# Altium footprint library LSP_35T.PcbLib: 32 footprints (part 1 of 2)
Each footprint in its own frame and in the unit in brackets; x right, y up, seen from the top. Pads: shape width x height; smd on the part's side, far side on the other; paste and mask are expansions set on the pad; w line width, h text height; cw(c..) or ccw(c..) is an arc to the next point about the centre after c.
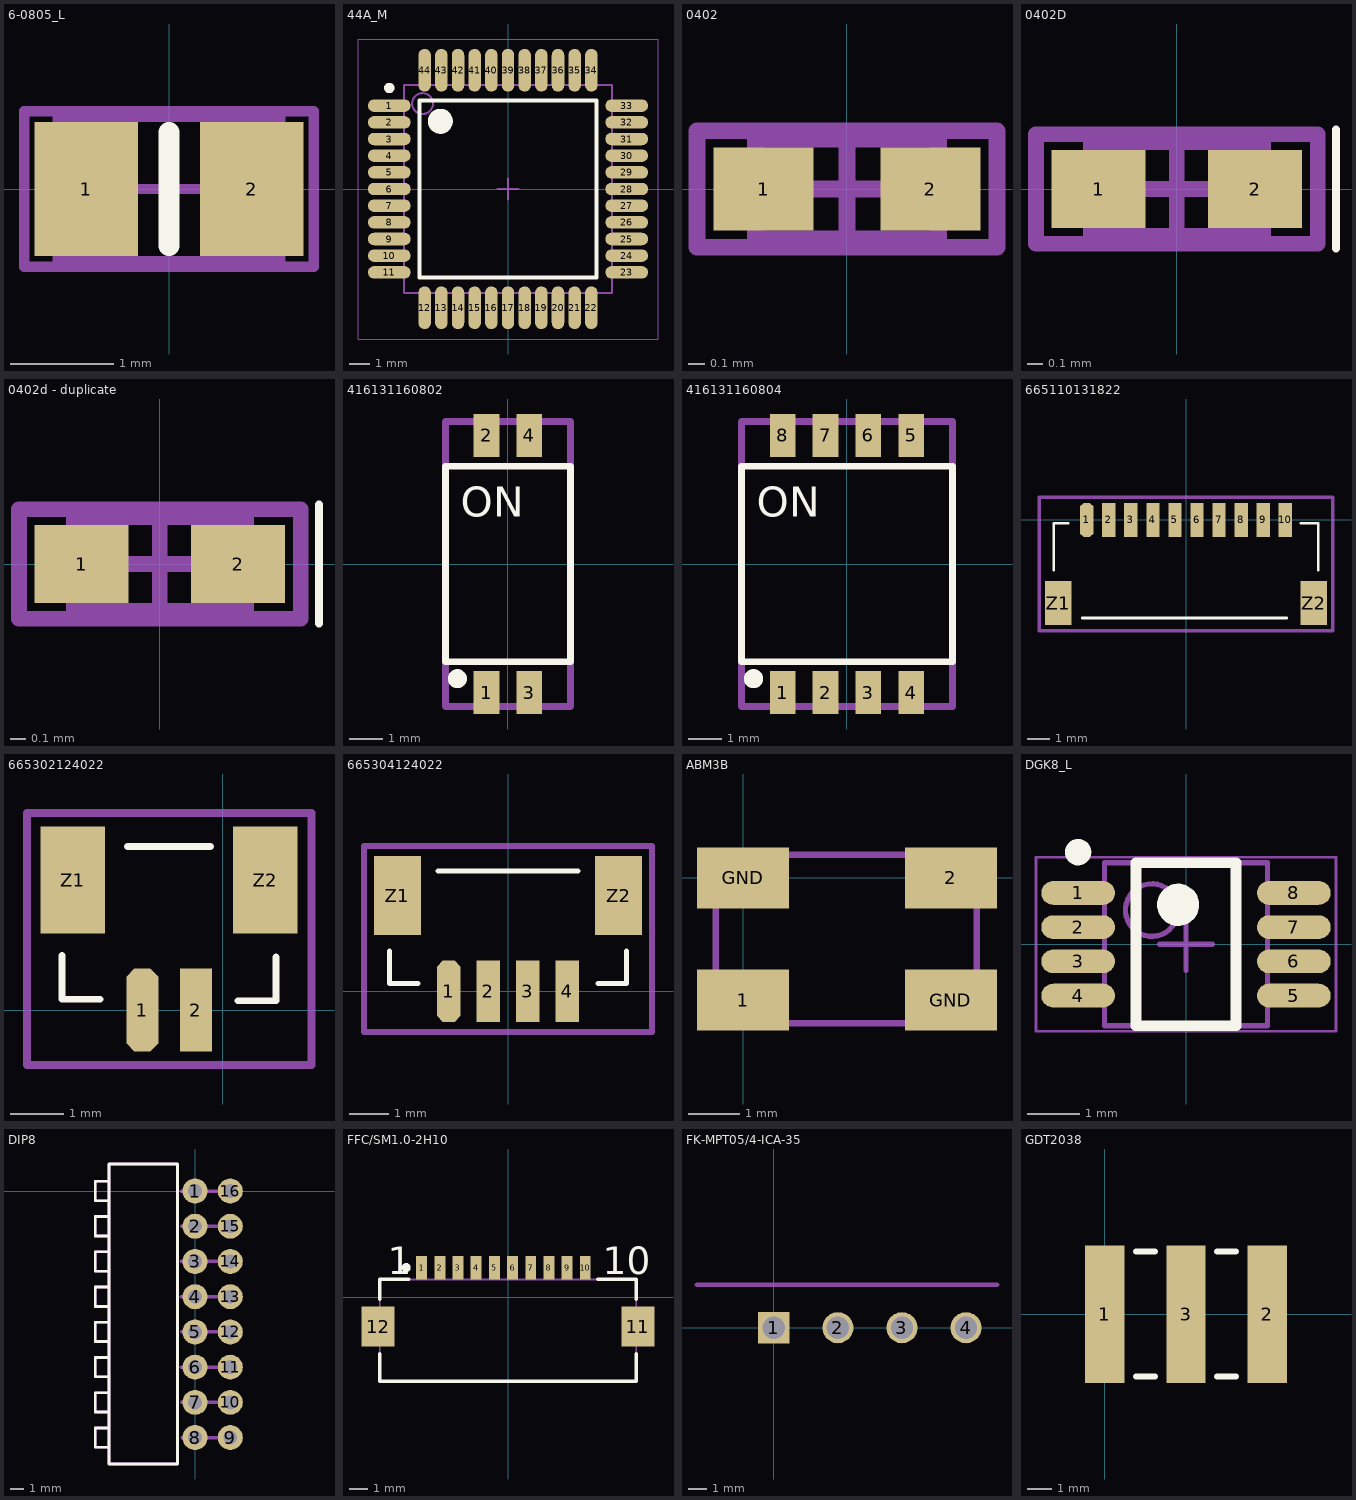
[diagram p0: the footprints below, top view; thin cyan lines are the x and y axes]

## 6-0805_L [mm] "Chip Resistor, Body 2.0x1.2mm, IPC High Density"
height 0.7
pads (2):
  rect 1x1.3 smd: 1(-0.8,0) 2(0.8,0)
Top Overlay:
  lines w0.2: 0,-0.55 0,0.55
Mechanical 13:
  lines w0.1: -1.075,-0.7 -1.075,0.7 1.075,0.7 1.075,-0.7 -1.075,-0.7
Mechanical 15:
  lines w0.1: -0.5,0 0.5,0 ; 0,-0.5 0,0.5 ; -1.4,-0.75 -1.4,0.75 1.4,0.75 1.4,-0.75 -1.4,-0.75
3D body: height 0.7, standoff 0, extent -1.075,-0.7 1.075,0.7

## 44A_M [mm] "Thin QFP, 44-Leads, Body 10x10mm, Pitch 0.8mm, IPC Low Density"
height 1.2
pads (44):
  oval 2.05x0.6 smd: 1(-5.7,4) 2(-5.7,3.2) 3(-5.7,2.4) 4(-5.7,1.6) 5(-5.7,0.8) 6(-5.7,0) 7(-5.7,-0.8) 8(-5.7,-1.6) 9(-5.7,-2.4) 10(-5.7,-3.2) 11(-5.7,-4) 23(5.7,-4) 24(5.7,-3.2) 25(5.7,-2.4) 26(5.7,-1.6) 27(5.7,-0.8) 28(5.7,0) 29(5.7,0.8) 30(5.7,1.6) 31(5.7,2.4) 32(5.7,3.2) 33(5.7,4)
  oval 0.6x2.05 smd: 12(-4,-5.7) 13(-3.2,-5.7) 14(-2.4,-5.7) 15(-1.6,-5.7) 16(-0.8,-5.7) 17(0,-5.7) 18(0.8,-5.7) 19(1.6,-5.7) 20(2.4,-5.7) 21(3.2,-5.7) 22(4,-5.7) 34(4,5.7) 35(3.2,5.7) 36(2.4,5.7) 37(1.6,5.7) 38(0.8,5.7) 39(0,5.7) 40(-0.8,5.7) 41(-1.6,5.7) 42(-2.4,5.7) 43(-3.2,5.7) 44(-4,5.7)
Top Overlay:
  circle w0.6: c-3.25,3.25 r0.3
  circle w0.25: c-5.7,4.85 r0.125
  lines w0.2: -4.25,-4.25 4.25,-4.25 4.25,4.25 -4.25,4.25 -4.25,-4.25
Mechanical 13:
  circle w0.1: c-4.1,4.1 r0.5
  lines w0.1: -5,-5 5,-5 5,5 -5,5 -5,-5
Mechanical 15:
  lines w0.05: -7.2,-7.2 7.2,-7.2 7.2,7.2 -7.2,7.2 -7.2,-7.2
  lines w0.1: -0.5,0 0.5,0 ; 0,-0.5 0,0.5
3D body: height 1.2, standoff 0, extent -5,-5 5,5

## 0402 [mm] "Chip Capacitor, Body 1.0x0.5mm, IPC High Density"
height 1.3
pads (2):
  rect 0.6x0.5 smd: 1(-0.5,0) 2(0.5,0)
Mechanical 13:
  lines w0.1: -0.55,-0.3 -0.55,0.3 0.55,0.3 0.55,-0.3 -0.55,-0.3
Mechanical 15:
  lines w0.1: -0.3,0 0.3,0 ; 0,-0.3 0,0.3 ; -0.9,-0.35 -0.9,0.35 0.9,0.35 0.9,-0.35 -0.9,-0.35
3D body: height 1.3, standoff 0, extent -0.55,-0.3 0.55,0.3

## 0402D [mm] "Diode, Body 1.0x0.5mm, IPC High Density"
height 1.3
pads (2):
  rect 0.6x0.5 smd: 1(-0.5,0) 2(0.5,0)
Top Overlay:
  lines w0.051: 1.016,-0.381 1.016,0.381
Mechanical 13:
  lines w0.1: -0.55,-0.3 0.55,-0.3 0.55,0.3 -0.55,0.3 -0.55,-0.3
Mechanical 15:
  lines w0.1: -0.3,0 0.3,0 ; 0,-0.3 0,0.3 ; -0.9,-0.35 0.9,-0.35 0.9,0.35 -0.9,0.35 -0.9,-0.35

## 0402d - duplicate [mm]
pads (2):
  rect 0.6x0.5 smd: 1(-0.5,0) 2(0.5,0)
Top Overlay:
  lines w0.051: 1.016,-0.381 1.016,0.381
Mechanical 13:
  lines w0.1: -0.55,-0.3 0.55,-0.3 0.55,0.3 -0.55,0.3 -0.55,-0.3
Mechanical 15:
  lines w0.1: -0.3,0 0.3,0 ; 0,-0.3 0,0.3 ; -0.9,-0.35 0.9,-0.35 0.9,0.35 -0.9,0.35 -0.9,-0.35

## 416131160802 [mm] "1.27 mm small compact SMD flat actuator with top tape, 02p"
height 2.5
pads (4):
  rect 0.76x1.27 smd: 1(-0.635,-3.81) 2(-0.635,3.81) 3(0.635,-3.81) 4(0.635,3.81)
Top Overlay:
  circle w0.5: c-1.5,-3.4 r0.032
  lines w0.2: -1.855,-2.9 1.855,-2.9 1.855,2.9 -1.855,2.9 -1.855,-2.9
  text "ON" at -1.4,1.4 h0.89
Mechanical 13:
  lines w0.2: -1.855,-4.22 1.855,-4.22 1.855,4.22 -1.855,4.22 -1.855,-4.22
3D body: height 2.7, standoff 0, extent -1.855,-4.22 1.855,4.22

## 416131160804 [mm] "1.27 mm small compact SMD flat actuator with top tape, 04p"
height 2.5
pads (8):
  rect 0.76x1.27 smd: 1(-1.905,-3.81) 2(-0.635,-3.81) 3(0.635,-3.81) 4(1.905,-3.81) 5(1.905,3.81) 6(0.635,3.81) 7(-0.635,3.81) 8(-1.905,3.81)
Top Overlay:
  circle w0.5: c-2.77,-3.4 r0.032
  lines w0.2: -3.125,-2.9 -3.125,2.9 3.125,2.9 3.125,-2.9 -3.125,-2.9
  text "ON" at -2.67,1.4 h0.89
Mechanical 13:
  lines w0.2: -3.125,-4.22 -3.125,4.22 3.125,4.22 3.125,-4.22 -3.125,-4.22
3D body: height 2.7, standoff 0, extent -3.125,-4.22 3.125,4.22

## 665110131822 [mm] "ConWTB Wire-to-Board Connectors 1.00 mm SMT Male Horizontal Shrouded Header, 10 pins - Tape & Reel"
height 2.9
pads (12):
  oct 0.6x1.55 smd: 1(-4.5,0)
  rect 0.6x1.55 smd: 2(-3.5,0) 3(-2.5,0) 4(-1.5,0) 5(-0.5,0) 6(0.5,0) 7(1.5,0) 8(2.5,0) 9(3.5,0) 10(4.5,0)
  rect 1.2x2 smd: Z1(-5.8,-3.775) Z2(5.8,-3.775)
Top Overlay:
  lines w0.12: -6,-2.286 -6,-0.15 -5.334,-0.15 ; -4.699,-4.445 4.572,-4.445 ; 5.207,-0.15 6,-0.15 6,-2.286
Mechanical 15:
  lines w0.152: -6.65,-5.025 6.65,-5.025 6.65,1.025 -6.65,1.025 -6.65,-5.025
3D body: height 2.95, standoff -0.02, extent -6,-4.4 6,0.55

## 665302124022 [mm] "ConWTB Wire-to-Board Connectors 1.00 mm SMT Male Vertical Shrouded Header, 4 pins - Tape & Reel with Cap"
height 4.25
pads (4):
  oct 0.6x1.55 smd: 1(-1.5,0)
  rect 0.6x1.55 smd: 2(-0.5,0)
  rect 1.2x2 smd: Z1(-2.8,2.425) Z2(0.793,2.425)
Top Overlay:
  lines w0.127: -3,1.016 -3,0.2 -2.286,0.2 ; -1.778,3.048 -0.229,3.048 ; 0.279,0.175 0.993,0.175 0.993,0.991
Mechanical 15:
  lines w0.152: -3.65,-1.025 1.651,-1.025 1.651,3.675 -3.65,3.675 -3.65,-1.025

## 665304124022 [mm] "ConWTB Wire-to-Board Connectors 1.00 mm SMT Male Vertical Shrouded Header, 4 pins - Tape & Reel with Cap"
height 4.25
pads (6):
  oct 0.6x1.55 smd: 1(-1.5,0)
  rect 0.6x1.55 smd: 2(-0.5,0) 3(0.5,0) 4(1.5,0)
  rect 1.2x2 smd: Z1(-2.8,2.425) Z2(2.8,2.425)
Top Overlay:
  lines w0.127: -3,1.016 -3,0.2 -2.286,0.2 ; -1.778,3.048 1.778,3.048 ; 2.286,0.2 3,0.2 3,1.016
Mechanical 15:
  lines w0.152: -3.65,-1.025 -3.65,3.675 3.65,3.675 3.65,-1.025 -3.65,-1.025
3D body: height 5.09, standoff -0.04, extent -3,-0.9 3,3.6

## ABM3B [mil]
height 50
pads (4):
  rect 71x47 smd: 1(0,-94) 2(160,0) GND(0,0) GND(160,-94)
Mechanical 15:
  lines w5: -21,-112 -21,18 179,18 ; -20,-112 180,-112 180,18

## DGK8_L [mm] "TSOP, 8-Leads, Body 3x3mm, Pitch 0.65mm, IPC High Density"
height 1.1
pads (8):
  oval 1.4x0.45 smd: 1(-2.05,0.975) 2(-2.05,0.325) 3(-2.05,-0.325) 4(-2.05,-0.975) 5(2.05,-0.975) 6(2.05,-0.325) 7(2.05,0.325) 8(2.05,0.975)
Top Overlay:
  circle w0.25: c-2.05,1.75 r0.125
  circle w0.4: c-0.15,0.75 r0.2
  lines w0.2: -0.95,-1.55 -0.95,1.55 0.95,1.55 0.95,-1.55 -0.95,-1.55
Mechanical 13:
  circle w0.1: c-0.65,0.65 r0.5
  lines w0.1: -1.55,-1.55 -1.55,1.55 1.55,1.55 1.55,-1.55 -1.55,-1.55
Mechanical 15:
  lines w0.05: -2.85,-1.65 -2.85,1.65 2.85,1.65 2.85,-1.65 -2.85,-1.65
  lines w0.1: -0.5,0 0.5,0 ; 0,-0.5 0,0.5
3D body: height 1.1, standoff 0.05, extent -1.55,-1.55 1.55,1.55

## DIP8 [mm]
pads (16):
  round 1.8 hole 1: 1(0,0) 2(0,-2.54) 3(0,-5.08) 4(0,-7.62) 5(0,-10.16) 6(0,-12.7) 7(0,-15.24) 8(0,-17.78) 9(2.54,-17.78) 10(2.54,-15.24) 11(2.54,-12.7) 12(2.54,-10.16) 13(2.54,-7.62) 14(2.54,-5.08) 15(2.54,-2.54) 16(2.54,0)
Top Overlay:
  lines w0.2: -6.2,-18.48 -7.2,-18.48 -7.2,-17.08 -6.2,-17.08 ; -6.2,-15.94 -7.2,-15.94 -7.2,-14.54 -6.2,-14.54 ; -6.2,-13.4 -7.2,-13.4 -7.2,-12 -6.2,-12 ; -6.2,-10.86 -7.2,-10.86 -7.2,-9.46 -6.2,-9.46 ; -6.2,-8.32 -7.2,-8.32 -7.2,-6.92 -6.2,-6.92 ; -6.2,-5.78 -7.2,-5.78 -7.2,-4.38 -6.2,-4.38 ; -6.2,-3.24 -7.2,-3.24 -7.2,-1.84 -6.2,-1.84 ; -6.2,-0.7 -7.2,-0.7 -7.2,0.7 -6.2,0.7 ; -6.2,-19.685 -6.2,1.95 -1.27,1.95 -1.27,-19.685 -6.2,-19.685
Mechanical 2:
  lines w0.2: -6.2,-18.48 -7.2,-18.48 -7.2,-17.08 -6.2,-17.08 ; -6.2,-15.94 -7.2,-15.94 -7.2,-14.54 -6.2,-14.54 ; -6.2,-13.4 -7.2,-13.4 -7.2,-12 -6.2,-12 ; -6.2,-10.86 -7.2,-10.86 -7.2,-9.46 -6.2,-9.46 ; -6.2,-8.32 -7.2,-8.32 -7.2,-6.92 -6.2,-6.92 ; -6.2,-5.78 -7.2,-5.78 -7.2,-4.38 -6.2,-4.38 ; -6.2,-3.24 -7.2,-3.24 -7.2,-1.84 -6.2,-1.84 ; -6.2,-0.7 -7.2,-0.7 -7.2,0.7 -6.2,0.7 ; -6.2,-19.685 -6.2,1.95 -1.27,1.95 -1.27,-19.685 -6.2,-19.685
  lines w0.254: -1,-12.7 2.54,-12.7 ; -1,0 2.54,0 ; -0.98,-7.62 2.54,-7.62 ; -0.98,-5.08 2.54,-5.08 ; -0.96,-15.24 2.54,-15.24 ; -0.96,-10.16 2.54,-10.16 ; -0.96,-2.54 2.54,-2.54 ; -0.92,-17.78 2.54,-17.78

## FFC/SM1.0-2H10 [mm] "Connector; FH12 Series; 10 Position; 1.0mm Spaced Bottom Eccentric Contact"
height 2
pads (12):
  rect 0.6x1.3 smd: 1(-4.75,1.625) 2(-3.75,1.625) 3(-2.75,1.625) 4(-1.75,1.625) 5(-0.75,1.625) 6(0.25,1.625) 7(1.25,1.625) 8(2.25,1.625) 9(3.25,1.625) 10(4.25,1.625)
  rect 1.8x2.2 smd: 11(7.15,-1.625) 12(-7.15,-1.625)
Top Overlay:
  circle w0.25: c-5.6,1.625 r0.125
  lines w0.2: -7.05,-3.125 -7.05,-4.625 7.05,-4.625 7.05,-3.125 ; -7.05,-0.125 -7.05,0.975 -5.45,0.975 ; 4.95,0.975 7.05,0.975 7.05,-0.125
  text "1" at -6.604,1.27 h1.5
  text "10" at 5.207,1.27 h1.5
Mechanical 13:
  lines w0.1: -7.05,-4.625 7.05,-4.625 7.05,0.975 -7.05,0.975 -7.05,-4.625
3D body: height 2, standoff 0, extent -7.05,-4.625 7.05,0.975

## FK-MPT05/4-ICA-35 [mm]
pads (4):
  rect 1.7x1.7 hole 1.219: 1(0,0)
  round 1.7 hole 1.219: 2(3.5,0) 3(7,0) 4(10.5,0)
Mechanical 15:
  lines w0.254: -4.191,2.35 12.192,2.35

## GDT2038 [mil]
height 197
pads (3):
  rect 63x220 smd: 1(0,0) 2(260,0) 3(130,0)
Top Overlay:
  lines w10: 50,-100 80,-100 ; 50,100 80,100 ; 180,-100 210,-100 ; 180,100 210,100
